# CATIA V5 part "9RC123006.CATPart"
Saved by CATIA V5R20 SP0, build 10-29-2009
Part number: 9RC123006
Revision: ANY
Definition: UNKNOWN
Nomenclature: 9RC123006
Source: Unknown
Bounding box of the stored display mesh (mm): x -24 to 6, y -6 to 6, z -2.35 to 2.35
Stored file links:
  C:\Users\Utente\Desktop\IO LAVORO\3D X SITO CF\CUMSA\3D files RC\RC 123006\9RC123006.CATPart
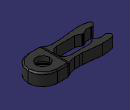
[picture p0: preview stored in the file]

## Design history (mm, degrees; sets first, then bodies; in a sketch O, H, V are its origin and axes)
Body1 "Chaflán1" (main body)
  Solid1: solid without history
